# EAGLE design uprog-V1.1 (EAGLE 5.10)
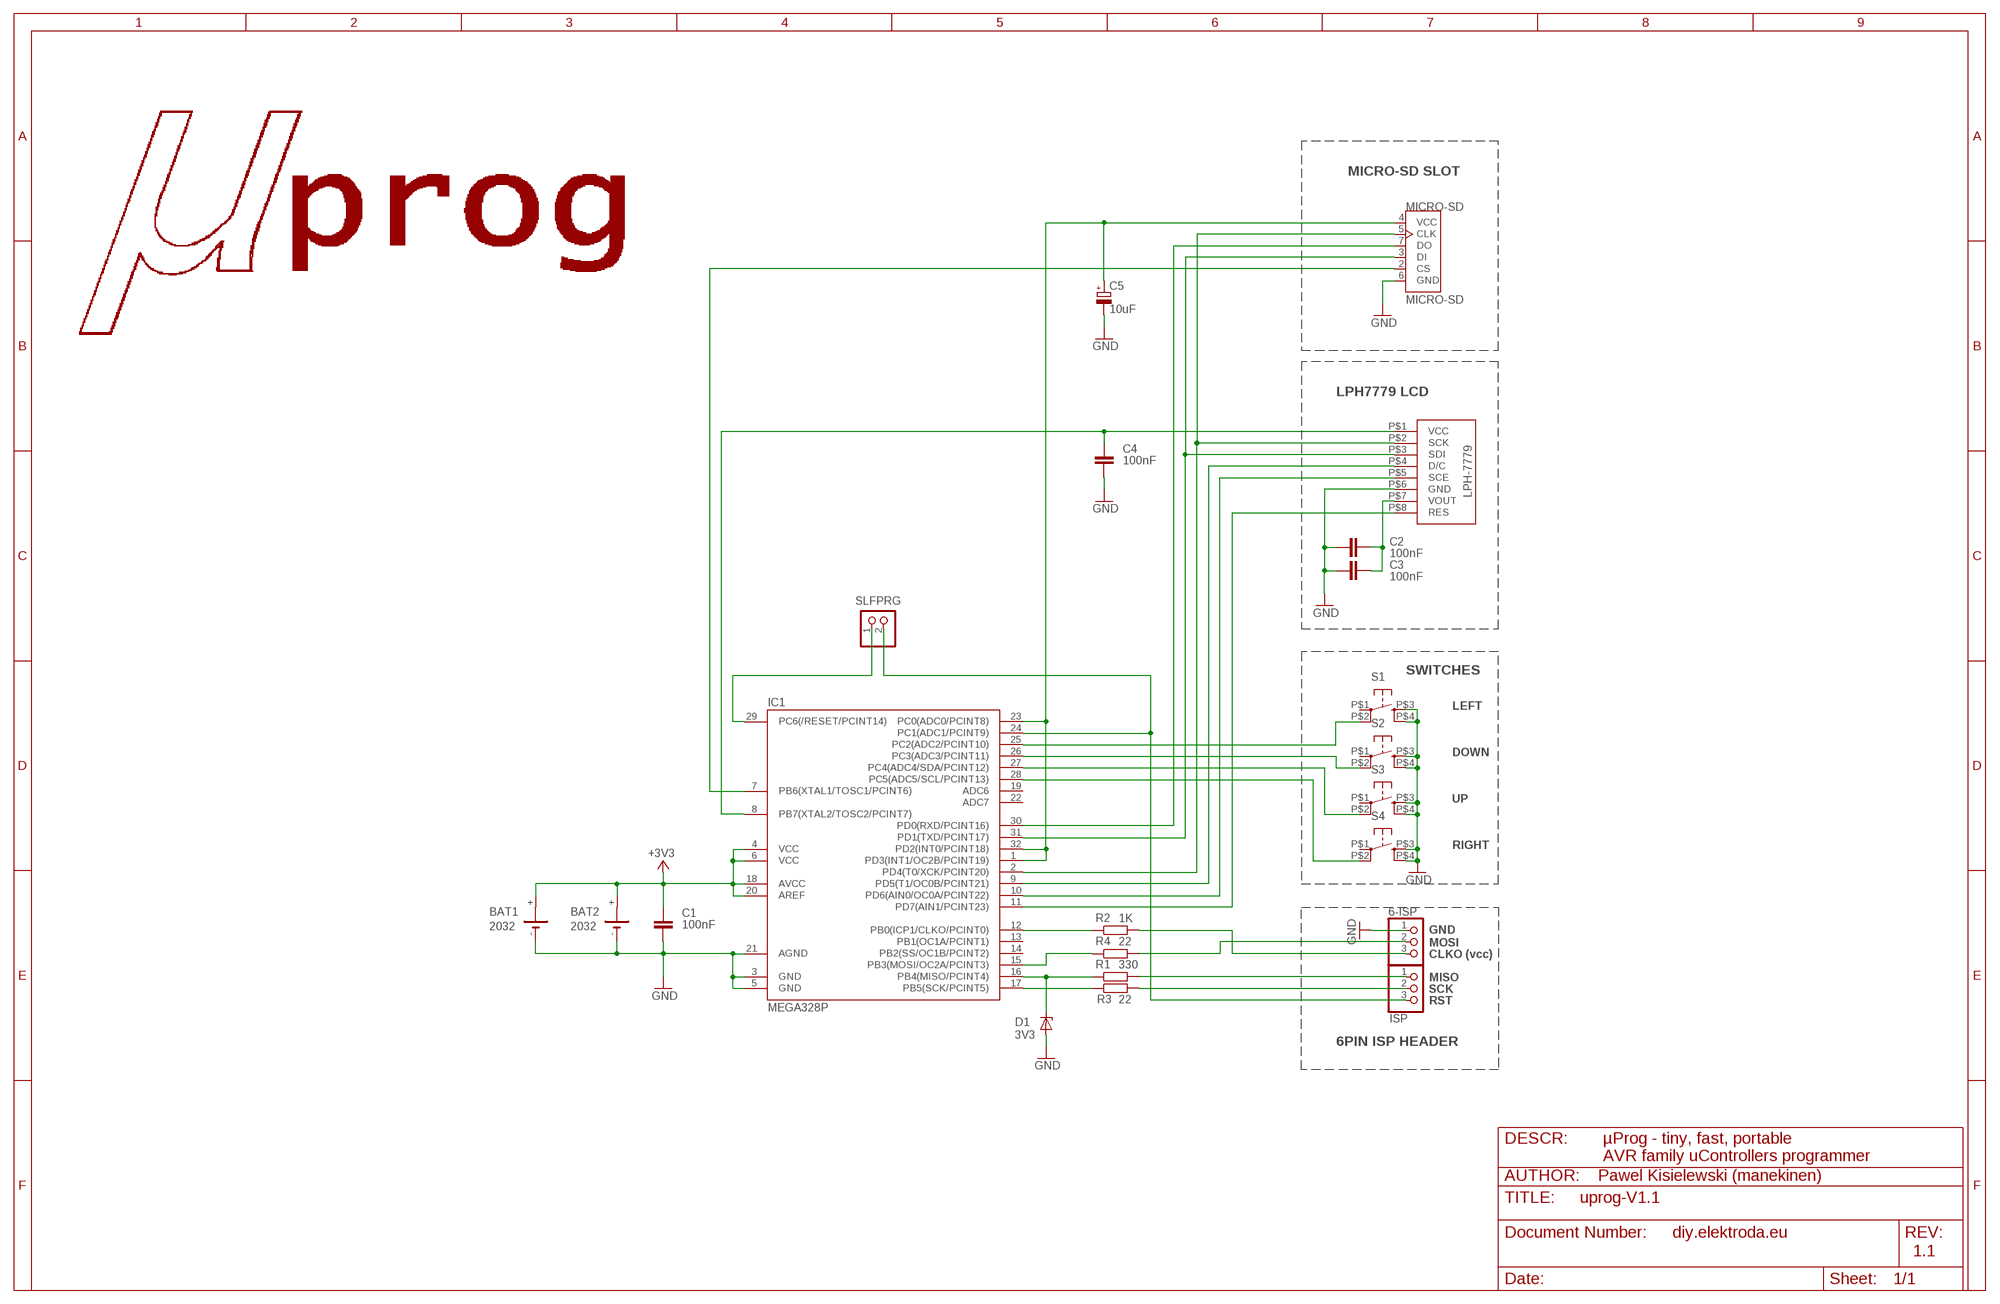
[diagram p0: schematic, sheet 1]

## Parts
6-ISP  PINHD-1X03_2.54-SMD-90°  [1X03SMD/90]
BAT1  2032  [KZH20SMD]
BAT2  2032  [KZH20SMD]
C1  100nF  C-EUC0805  [C0805]
C2  100nF  C-EUC0805  [C0805]
C3  100nF  C-EUC0805  [C0805]
C4  100nF  C-EUC0805  [C0805]
C5  10uF  CPOL-EUC/6032-28R  [C/6032-28R]
D1  3V3  ZENER-DIODESOD80C  [SOD80C]
IC1  MEGA328P  MEGA48/88/168-AU  [TQFP32-08]
ISP  PINHD-1X03_2.54-SMD-90°  [1X03SMD/90]
MICRO-SD  MICRO-SD  SF-MICROSD  [MICROSD]
R1  330  R-EU_R0805  [R0805]
R2  1K  R-EU_R0805  [R0805]
R3  22  R-EU_R0805  [R0805]
R4  22  R-EU_R0805  [R0805]
S1  10-XX-SMD  [B3F-10XX-SMD]
S2  10-XX-SMD  [B3F-10XX-SMD]
S3  10-XX-SMD  [B3F-10XX-SMD]
S4  10-XX-SMD  [B3F-10XX-SMD]
SLFPRG  PINHD-1X02_2.54  [1X02]
U$1  NOKIA3310  [NOKIA]

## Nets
+3V3: BAT1.+ BAT2.+ C1.1 IC1.4(VCC) IC1.6(VCC) IC1.18(AVCC) IC1.20(AREF)
GND: 6-ISP.1 BAT1.- BAT2.- C1.2 C2.2 C3.2 C4.2 C5.- D1.A IC1.3(GND) IC1.5(GND) IC1.21(AGND) MICRO-SD.6(GND) S1.P$3(S) S1.P$4(S1) S2.P$3(S) S2.P$4(S1) S3.P$3(S) S3.P$4(S1) S4.P$3(S) S4.P$4(S1) U$1.P$6(GND)
LCD-RES: IC1.11(PD7(AIN1/PCINT23)) U$1.P$8(RES)
LCD-SCE: IC1.10(PD6(AIN0/OC0A/PCINT22)) U$1.P$5(SCE)
LCD-VCC: C4.1 IC1.8(PB7(XTAL2/TOSC2/PCINT7)) U$1.P$1(VCC)
MISO2: IC1.30(PD0(RXD/PCINT16)) MICRO-SD.7(DO)
MISO_B: ISP.1 R1.2
MOSI: IC1.15(PB3(MOSI/OC2A/PCINT3)) R4.1
MOSI2: IC1.31(PD1(TXD/PCINT17)) MICRO-SD.3(DI) U$1.P$3(SDI)
N$1: 6-ISP.2
N$2: IC1.12(PB0(ICP1/CLKO/PCINT0)) R2.1
N$3: D1.C IC1.16(PB4(MISO/PCINT4)) R1.1
N$4: IC1.9(PD5(T1/OC0B/PCINT21)) U$1.P$4(D/C)
N$18: 6-ISP.3 R2.2
N$22: IC1.28(PC5(ADC5/SCL/PCINT13)) S4.P$2(P1)
N$23: IC1.27(PC4(ADC4/SDA/PCINT12)) S3.P$2(P1)
N$24: IC1.26(PC3(ADC3/PCINT11)) S2.P$2(P1)
N$25: IC1.25(PC2(ADC2/PCINT10)) S1.P$2(P1)
RESET: IC1.29(PC6(/RESET/PCINT14)) SLFPRG.1
RST: IC1.24(PC1(ADC1/PCINT9)) ISP.3 SLFPRG.2
SCK: IC1.17(PB5(SCK/PCINT5)) R3.1
SCK2: IC1.2(PD4(T0/XCK/PCINT20)) MICRO-SD.5(CLK) U$1.P$2(SCK)
SCK_B: ISP.2
SD-CS: IC1.7(PB6(XTAL1/TOSC1/PCINT6)) MICRO-SD.2(CS)
SD-VCC: C5.+ IC1.1(PD3(INT1/OC2B/PCINT19)) IC1.23(PC0(ADC0/PCINT8)) IC1.32(PD2(INT0/PCINT18)) MICRO-SD.4(VCC)
VOUT: C2.1 C3.1 U$1.P$7(VOUT)
Unconnected: IC1.13(PB1(OC1A/PCINT1)) IC1.14(PB2(SS/OC1B/PCINT2)) IC1.19(ADC6) IC1.22(ADC7) R3.2 R4.2 S1.P$1(P) S2.P$1(P) S3.P$1(P) S4.P$1(P)

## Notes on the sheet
- MICRO-SD SLOT
- LPH7779 LCD
- SWITCHES
- LEFT
- DOWN
- UP
- RIGHT
- GND
- MOSI
- CLKO (vcc)
- MISO
- SCK
- RST
- 6PIN ISP HEADER
- DESCR: | µProg - tiny, fast, portable
- AVR family uControllers programmer
- AUTHOR:    Pawel Kisielewski (manekinen)
- diy.elektroda.eu
- 1.1

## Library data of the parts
6-ISP ISP = pinhead-2:PINHD-1X03: PIN HEADER
BAT1 BAT2 = kzh20_lithium_batterie_holder:2032
C1-C4 = rcl:C-EU: CAPACITOR, European symbol
C5 = rcl:CPOL-EU: POLARIZED CAPACITOR, European symbol
D1 = diode:ZENER-DIODE: Z-Diode
IC1 = avr-6:MEGA48/88/168
MICRO-SD = microsd:SF-MICROSD
R1-R4 = rcl:R-EU_: RESISTOR, European symbol
S1-S4 = switch-omron:10-XX-SMD
SLFPRG = pinhead-2:PINHD-1X02: PIN HEADER
U$1 = Nokia3310:NOKIA3310

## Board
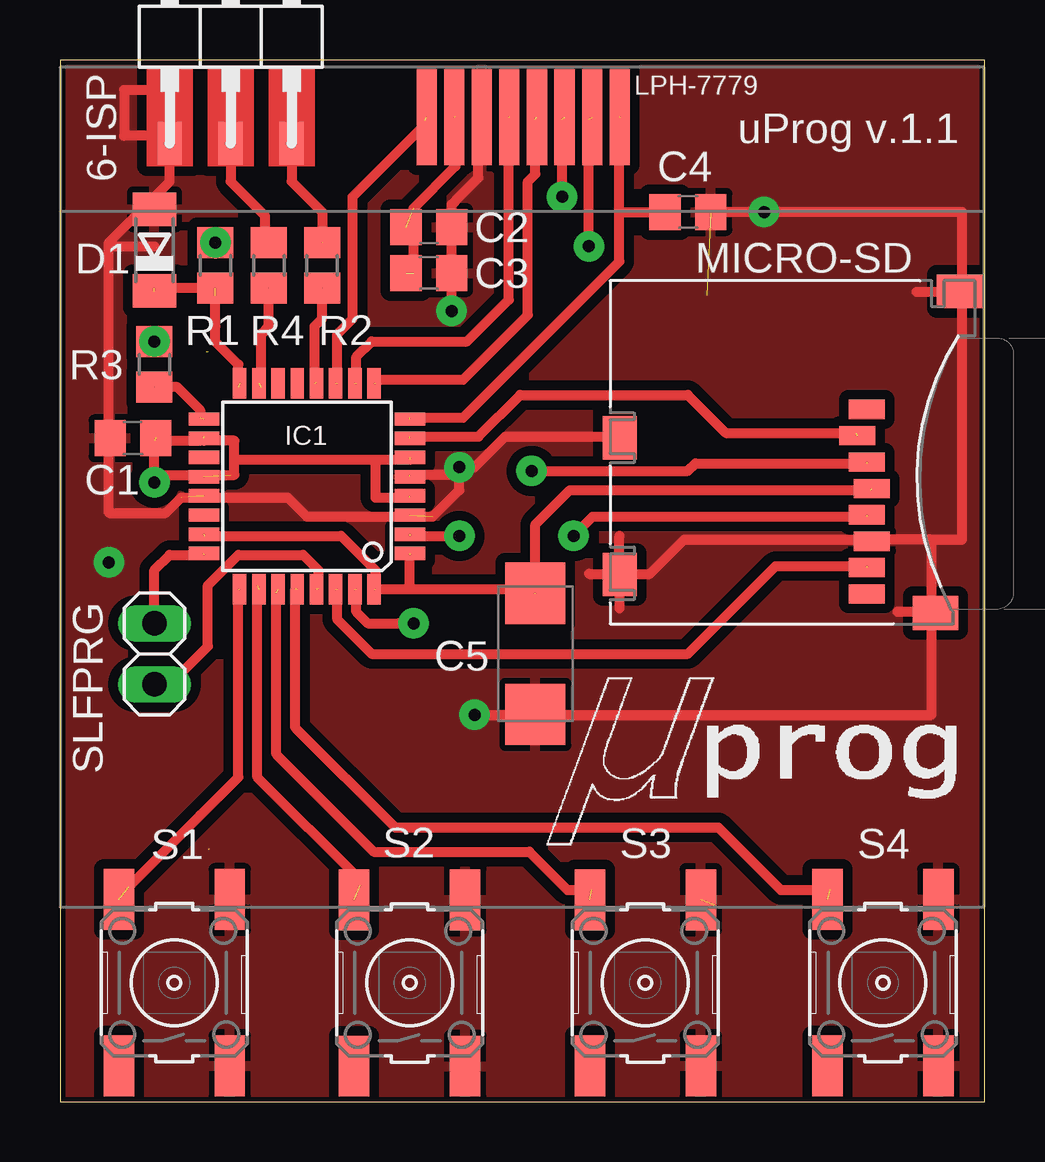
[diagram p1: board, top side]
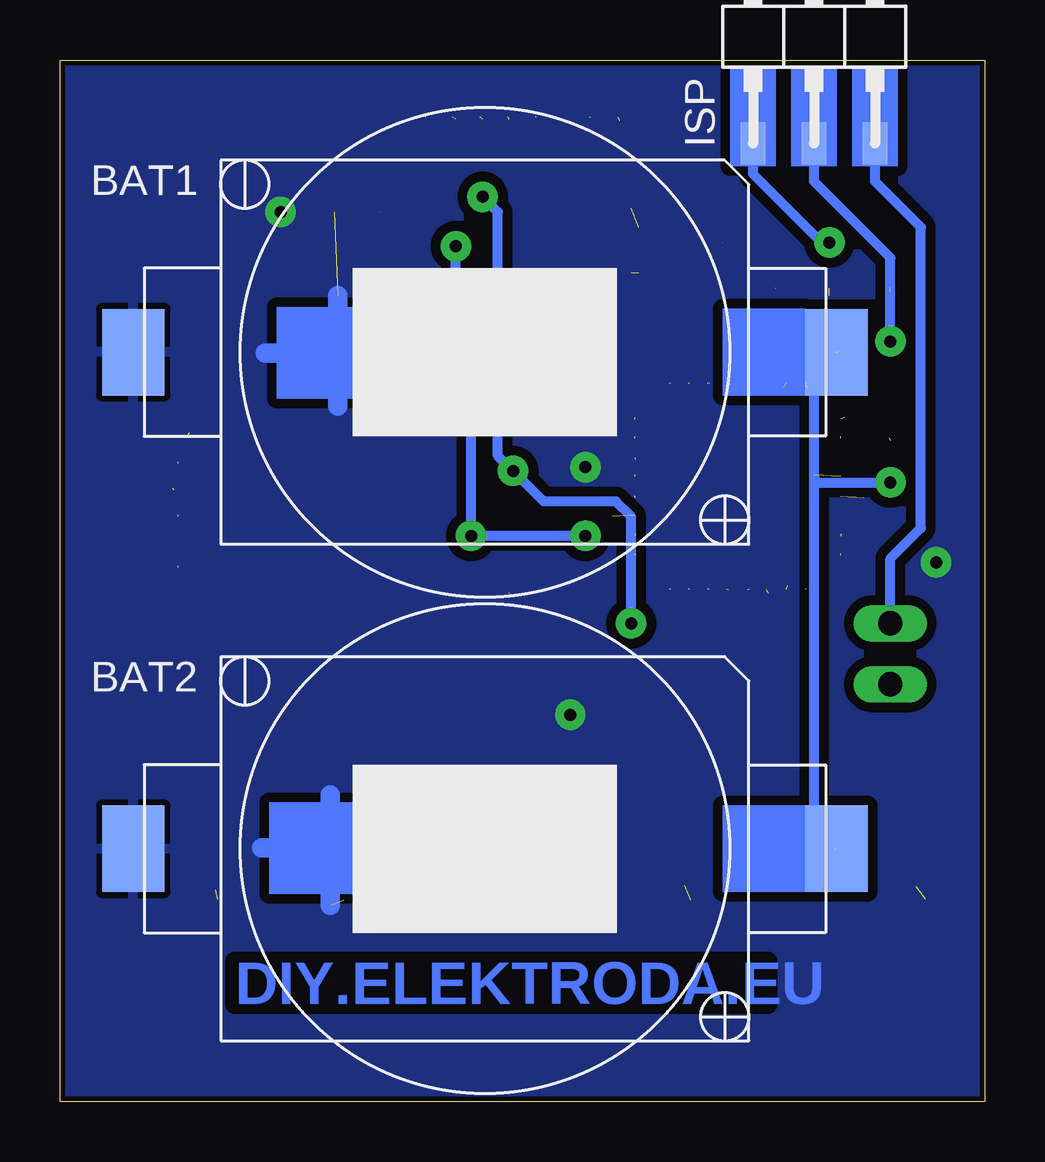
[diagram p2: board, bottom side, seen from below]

Size 38.53 x 43.42 mm. Coordinates in mm from the lower left corner, seen from the top.
Outline: 0,0 38.53,0 38.53,43.42 0,43.42 0,0
Copper layers (1*16): Top 0.035mm / dielectric 1.5mm / Bottom 0.035mm
Design rules "default *": minimum track width 10mil, minimum drill 24mil, track to track 16mil, track to pad 16mil, pad to pad 16mil, via to via 16mil, smd to smd 16mil, copper to edge 8mil, drill to drill 8mil, minimum pad ring 10mil, minimum via ring 8mil, stop-mask expansion 4mil, vias tented up to drill 0mil, thermal gap 10mil

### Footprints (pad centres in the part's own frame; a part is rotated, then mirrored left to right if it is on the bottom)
1X03SMD/90 = smd 1.016 x 1.778: 1 -1.27,-5.08; 2 1.27,-5.08; 3 3.81,-5.08
KZH20SMD = smd 2.6 x 3.6: + 14.65,0; - -14.65,0
C0805 = smd 1.3 x 1.5: 1 -0.95,0; 2 0.95,0
C/6032-28R = smd 2.55 x 2.5: + 2.525,0; - -2.525,0
SOD80C = smd 1.4 x 1.8: A 1.7,0; C -1.7,0
TQFP32-08 = smd 1.27 x 0.559: 1 -4.293,2.8; 2 -4.293,2; 3 -4.293,1.2; 4 -4.293,0.4; 5 -4.293,-0.4; 6 -4.293,-1.2; 7 -4.293,-2; 8 -4.293,-2.8; 17 4.293,-2.8; 18 4.293,-2; 19 4.293,-1.2; 20 4.293,-0.4; 21 4.293,0.4; 22 4.293,1.2; 23 4.293,2; 24 4.293,2.8 | smd 0.559 x 1.27: 9 -2.8,-4.293; 10 -2,-4.293; 11 -1.2,-4.293; 12 -0.4,-4.293; 13 0.4,-4.293; 14 1.2,-4.293; 15 2,-4.293; 16 2.8,-4.293; 25 2.8,4.293; 26 2,4.293; 27 1.2,4.293; 28 0.4,4.293; 29 -0.4,4.293; 30 -1.2,4.293; 31 -2,4.293; 32 -2.8,4.293
MICROSD = smd 0.8 x 1.5: 1 -1.94,2.7; 2 -0.84,2.3; 3 0.26,2.7; 4 1.36,2.9; 5 2.46,2.7; 6 3.56,2.9; 7 4.66,2.7; 8 5.76,2.7 | smd 1.4 x 1.9: NC -6.85,6.55; NC3 6.55,5.55 | smd 1.8 x 1.4: NC1 -0.75,-7.6; NC2 4.95,-7.6
R0805 = smd 1.3 x 1.5: 1 -0.95,0; 2 0.95,0
B3F-10XX-SMD = smd 2.54 x 1.27: P$1 -3.467,2.311; P$2 3.467,2.311; P$3 3.467,-2.311; P$4 -3.467,-2.311
1X02 = drill 1.016 long: 1 -1.27,0; 2 1.27,0
NOKIA = smd 0.838 x 4: P$1 4.026,2.01; P$2 2.874,2.01; P$3 1.718,2.01; P$4 0.57,2.01; P$5 -0.578,2.008; P$6 -1.732,2.008; P$7 -2.881,2.008; P$8 -4.03,2.008

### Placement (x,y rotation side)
6-ISP  5.84,45.02 0 top
BAT1  20.83,31.24 0 bottom
BAT2  20.83,10.54 0 bottom
C1  3.04,27.66 180 top
C2  15.37,36.45 0 top
C3  15.37,34.54 0 top
C4  26.16,37.08 0 top
C5  19.81,18.67 90 top
D1  3.94,35.5 90 top
IC1  10.29,25.65 180 top
ISP  8.38,45.02 0 bottom
MICRO-SD  30.92,26.92 270 top
R1  6.48,34.86 90 top
R2  10.92,34.86 90 top
R3  3.94,30.73 90 top
R4  8.7,34.86 90 top
S1  4.76,4.96 90 top
S2  14.57,4.95 90 top
S3  24.39,4.96 90 top
S4  34.29,4.96 90 top
SLFPRG  3.94,18.67 90 top
U$1  19.3,39.02 0 top

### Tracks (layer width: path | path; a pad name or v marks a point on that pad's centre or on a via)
+3V3  (via drill 0.5 pad 1.27)  (7 unrouted)
  Top 0.406: 7.27,26.77 7.27,26.13 3.94,26.13 v3.94,25.81 3.94,27.56 5.84,27.56 6,27.72 | 7.27,26.77 7.27,27.56 6,27.56 | 7.27,26.77 13.14,26.77 | 13.14,26.77 13.14,25.18 14.57,25.18 | 13.14,26.77 14.57,26.77
  Bottom 0.406: 6.22,10.54 7.11,11.43 7.11,25.02 7.11,26.13 7.11,25.81 | 7.11,25.81 v3.94,25.81 | 7.11,25.81 7.11,30.23 6.1,31.24
GND  (via drill 0.5 pad 1.27)  (5 unrouted)
  Top 0.406: 17.43,42.64 17.43,38.51 16.64,37.72 16.32,37.4 v16.32,32.96 | 6-ISP.1 4.57,38.35 2.03,35.81 2.03,35.66 | 2.03,35.66 2.03,24.54 4.41,24.54 5.05,25.18 9.49,25.18 10.29,24.38 15.53,24.38 16.64,25.5 v16.64,26.45 | 36.32,23.43 34.1,23.43 | v16.64,26.45 16.64,26.13 14.57,26.13 | 2.03,35.66 3.94,35.66 | 6-ISP.1 4.57,40.26 2.67,40.26 2.67,42.16 4.57,42.16 6-ISP.1 | 37.59,33.75 35.69,33.75 | 36.32,20.42 34.89,20.42 | 23.3,22 | 23.3,22 24.57,22 26,23.43 33.78,23.43 | 22.03,22 23.3,22 | 23.3,22 23.3,23.59 | 23.3,22 23.3,20.57 | 19.81,16.13 v17.27,16.13 36.32,16.13 36.32,20.42 | v16.64,26.45 17.27,26.45 18.54,27.72 23.3,27.72 | 36.32,20.42 36.32,23.43 | 37.59,33.75 37.59,23.43 36.32,23.43 | 37.59,33.75 37.59,37.08 v29.34,37.08 C4.2
  Bottom 0.813: 27.27,10.57 27.27,12.8 | 27.27,10.57 27.27,8.19 | 27.27,10.57 30.13,10.57 | 24.1,10.57 27.27,10.57 | 26.96,31.21 26.96,33.59 | 26.96,31.21 26.96,28.99 | 26.96,31.21 29.97,31.21 | 23.78,31.21 26.96,31.21
  other vias: 2.03,22.48
  pour Top: 0,43.43 0,0 38.54,0 38.54,43.43
  pour Bottom: 0,43.43 0,0 38.54,0 38.54,43.43
LCD-RES  (2 unrouted)
  Top 0.406: 11.56,29.94 11.56,32 12.19,32.64 12.19,37.72 15.21,40.74 15.21,40.89
LCD-SCE  (2 unrouted)
  Top 0.406: 12.35,29.94 12.35,31.05 12.99,31.69 16.95,31.69 18.7,33.43 18.7,41.05
LCD-VCC  (3 unrouted)
  Top 0.406: 14.57,28.51 16.8,28.51 23.3,35.02 23.3,37.08 | 23.3,37.08 23.3,41.05 | 23.3,37.08 C4.1
MISO2  (2 unrouted)
  Top 0.406: 11.56,21.37 11.56,20.1 12.99,18.67 26.16,18.67 29.81,22.32 33.62,22.32
MISO_B  (via drill 0.5 pad 1.27)  (1 unrouted)
  Top 0.406: v6.48,35.81 6.48,35.34
  Bottom 0.406: ISP.1 9.65,38.67 6.79,35.81 v6.48,35.81
MOSI  (2 unrouted)
  Top 0.406: R4.1 8.7,32.32 8.38,32 8.38,29.78
MOSI2  (via drill 0.5 pad 1.27)  (4 unrouted)
  Top 0.406: 12.35,21.37 12.35,20.42 12.83,19.94 14.1,19.94 v14.73,19.94 | v19.65,26.29 26.16,26.29 26.48,26.61 33.62,26.61 | v20.92,37.72 20.92,40.96
  Bottom 0.406: v20.92,37.72 20.29,37.08 20.29,26.92 v19.65,26.29 18.38,25.02 15.37,25.02 14.73,24.38 v14.73,19.94
N$1
  Top 0.406: 6-ISP.2 7.11,38.35 8.54,36.93 8.54,35.97
N$2  (2 unrouted)
  Top 0.406: 10.6,29.94 10.6,32.32 10.92,32.64 R2.1
N$3  (4 unrouted)
  Top 0.406: 6.48,32.32 6.48,33.59 | 7.43,29.78 7.43,30.73 6.48,31.69 R1.1 3.94,33.91
N$4  (2 unrouted)
  Top 0.406: 13.14,29.94 13.14,30.1 16.8,30.1 19.49,32.8 19.49,38.35 19.81,38.67 19.81,40.96
N$18  (1 unrouted)
  Top 0.406: 6-ISP.3 | 6-ISP.3 9.65,38.35 10.92,37.08 R2.2
N$22  (2 unrouted)
  Top 0.406: 32.07,8.83 30.04,8.83 27.43,11.43 13.97,11.43 9.81,15.59 9.81,21.37
N$23  (2 unrouted)
  Top 0.406: 22.16,8.83 21.15,8.83 19.56,10.41 13.08,10.41 9.02,14.48 9.02,21.21
N$24  (2 unrouted)
  Top 0.406: 12.51,9.02 12.51,9.24 8.22,13.53 8.22,21.53
N$25  (2 unrouted)
  Top 0.406: 2.86,9.02 2.86,8.95 5.84,11.94 7.43,13.53 7.43,21.37
RESET  (1 unrouted)
  Top 0.406: 10.76,21.37 10.76,22.16 10.13,22.8 7.43,22.8 6.16,21.53 6.16,18.99 4.57,17.4 SLFPRG.1
RST  (1 unrouted)
  Top 0.406: SLFPRG.2 3.94,22.16 4.57,22.8 6,22.8
  Bottom 0.406: ISP.3 4.57,38.35 2.67,36.45 2.67,23.91 3.94,22.64 SLFPRG.2
SCK  (2 unrouted)
  Top 0.406: R3.1 4.89,29.78 5.84,28.83 5.84,28.51
SCK2  (via drill 0.5 pad 1.27)  (4 unrouted)
  Top 0.406: v21.4,23.59 22.19,24.38 33.62,24.38 | v22.03,35.66 22.03,40.96 | v16.64,23.59 16.48,23.59 14.57,23.59
  Bottom 0.406: v22.03,35.66 22.03,33.75 21.4,33.12 v21.4,23.59 v16.64,23.59
SCK_B  (via drill 0.5 pad 1.27)
  Bottom 0.406: ISP.2 7.11,38.35 3.94,35.18 v3.94,31.69
SD-CS  (2 unrouted)
  Top 0.406: 33.15,27.88 27.75,27.88 26.16,29.46 19.18,29.46 17.43,27.72 14.57,27.72
SD-VCC  (5 unrouted)
  Top 0.406: 14.57,21.37 13.14,21.37 13.14,22.16 11.72,23.59 6,23.59 | 14.57,21.37 14.57,22.8 | 14.57,21.37 19.81,21.37 | 33.78,25.5 21.24,25.5 19.81,24.07 19.81,21.37 | 19.81,21.37 19.81,21.21
VOUT  (3 unrouted)
  Top 0.406: 16.48,41.05 16.48,38.99 14.73,37.24 14.73,34.54
(copper drawn outside any net)
  shapes: Bottom area x7, Top area x3

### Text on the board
Bottom: DIY.ELEKTRODA.EU
tPlace: uProg v.1.1
tNames: MICRO-SD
